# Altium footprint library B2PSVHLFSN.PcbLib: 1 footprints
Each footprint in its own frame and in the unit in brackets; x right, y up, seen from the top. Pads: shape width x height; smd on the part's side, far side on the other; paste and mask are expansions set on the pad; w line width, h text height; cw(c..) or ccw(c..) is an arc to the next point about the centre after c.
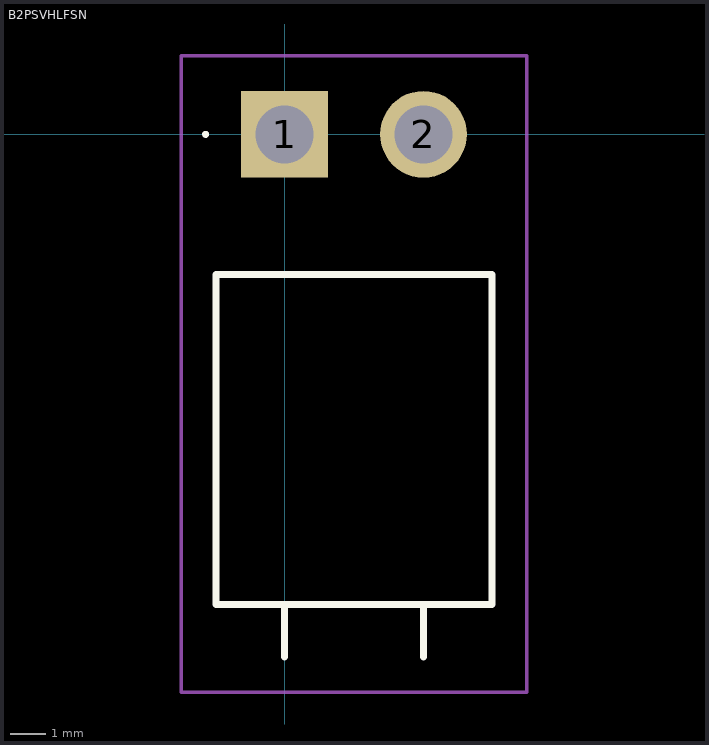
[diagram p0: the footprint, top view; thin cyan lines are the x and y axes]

## B2PSVHLFSN [mm]
pads (2):
  rect 2.475x2.475 hole 1.65: 1(0,0)
  round 2.475 hole 1.65: 2(3.96,0)
Top Overlay:
  lines w0.1: -2.3,0 cw(c-2.25,0) -2.2,0 ; -2.3,0 -2.3,0 ; -2.3,0 ccw(c-2.25,0) -2.2,0 ; -2.2,0 -2.2,0
  lines w0.2: 0,-14.9 0,-13.4 ; 3.96,-14.9 3.96,-13.4 ; -1.95,-13.4 5.91,-13.4 5.91,-4 -1.95,-4 -1.95,-13.4
Mechanical 15:
  lines w0.1: 0,-14.9 0,-13.4 ; 3.96,-14.9 3.96,-13.4 ; -1.95,-13.4 5.91,-13.4 5.91,-4 -1.95,-4 -1.95,-13.4
Mechanical 20:
  lines w0.1: -2.95,-15.9 6.91,-15.9 6.91,2.237 -2.95,2.237 -2.95,-15.9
